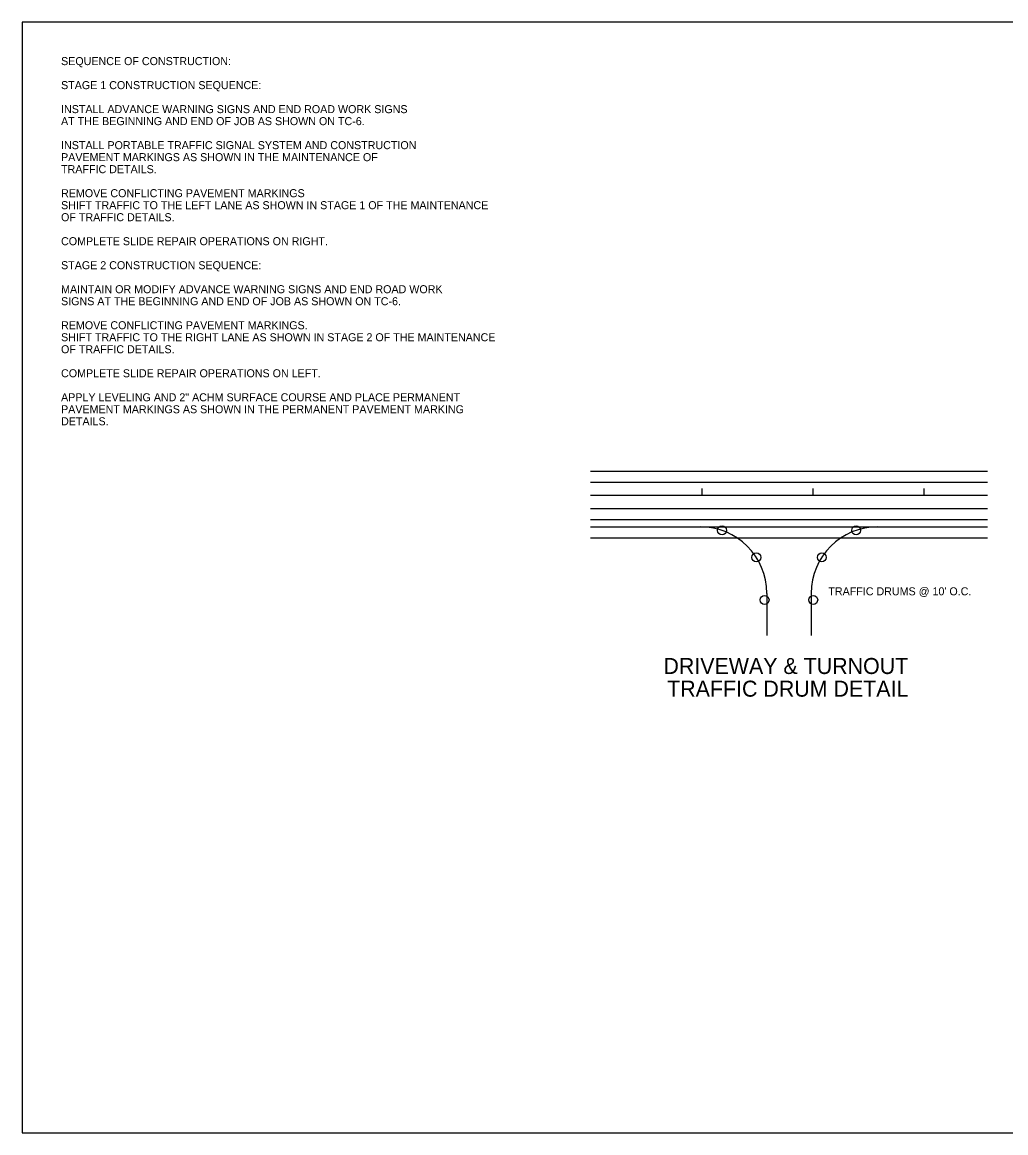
# Model space of a CAD drawing. Extents: x 1806907 to 1812607, y 675071 to 676228.
# Drawn here: x 1806907 to 1807792, y 675071 to 676070 of the extents above; entities that cross this region are included whole.
import ezdxf

# ---------------------------------------------------------------- set-up
doc = ezdxf.new("R2010")
doc.units = 0
for name, color, linetype in [('_STAGE 1 DRUMS', 7, 'Continuous'), ('Default', 7, 'Continuous'), ('DSN_DRFT_Named-Boundary', 7, 'Continuous'), ('DSN_DRWY_Driveway', 7, 'Continuous'), ('DSN_RDWY_Alignment', 7, 'Continuous'), ('DSN_RDWY_Alignment Annotation', 7, 'Continuous'), ('EX_DRIVEWAY', 7, 'Continuous'), ('S_PHOTO_CTL_ANNOT', 7, 'Continuous')]:
    doc.layers.add(name, color=color, linetype=linetype)

msp = doc.modelspace()

# ---------------------------------------------------------------- linework, layer by layer
at = {"layer": '_STAGE 1 DRUMS'}
for centre in [(1807536.68, 675613.14), (1807657.42, 675613.14), (1807567.54, 675588.86), (1807626.56, 675588.86), (1807575, 675550.51), (1807618.8, 675550.55)]:
    msp.add_circle(centre, 4, dxfattribs=at)
at = {"layer": 'DSN_DRFT_Named-Boundary'}
msp.add_lwpolyline([(1806906.68, 675071.2), (1808556.68, 675071.2), (1808556.68, 676070.26), (1806906.68, 676070.26)], close=True, dxfattribs=at)
at = {"layer": 'DSN_DRWY_Driveway'}
for p, q in [((1807418.43, 675616.44), (1807775.67, 675616.44)), ((1807418.43, 675606.44), (1807775.67, 675606.44))]:
    msp.add_line(p, q, dxfattribs=at)
at = {"layer": 'DSN_RDWY_Alignment'}
msp.add_line((1807418.43, 675644.68), (1807775.67, 675644.68), dxfattribs=at)
at = {"layer": 'DSN_RDWY_Alignment Annotation'}
for p, q in [((1807518.43, 675650.68), (1807518.43, 675644.68)), ((1807618.43, 675650.68), (1807618.43, 675644.68)), ((1807718.43, 675650.68), (1807718.43, 675644.68))]:
    msp.add_line(p, q, dxfattribs=at)
at = {"layer": 'EX_DRIVEWAY'}
for p, q in [((1807418.43, 675666.44), (1807775.67, 675666.44)), ((1807418.43, 675656.44), (1807775.67, 675656.44)), ((1807418.43, 675632.92), (1807775.67, 675632.92)), ((1807418.43, 675622.92), (1807775.67, 675622.92))]:
    msp.add_line(p, q, dxfattribs=at)
at = {"layer": 'S_PHOTO_CTL_ANNOT'}
for p, q in [((1807577.05, 675556.44), (1807577.05, 675518.44)), ((1807617.05, 675556.44), (1807617.05, 675518.44))]:
    msp.add_line(p, q, dxfattribs=at)
for centre, start, end in [((1807517.05, 675556.44), 0, 90), ((1807677.05, 675556.44), 90, 180)]:
    msp.add_arc(centre, 60, start, end, dxfattribs=at)

# ---------------------------------------------------------------- texts
at = {"layer": 'Default'}
for s, height, p in [('SEQUENCE OF CONSTRUCTION:', 7.2, (1806941.68, 676031.66)), ('STAGE 1 CONSTRUCTION SEQUENCE:', 7.2, (1806941.68, 676010.06)), ('INSTALL ADVANCE WARNING SIGNS AND END ROAD WORK SIGNS', 7.2, (1806941.68, 675988.46)), ('AT THE BEGINNING AND END OF JOB AS SHOWN ON TC-6.', 7.2, (1806941.68, 675977.66)), ('INSTALL PORTABLE TRAFFIC SIGNAL SYSTEM AND CONSTRUCTION', 7.2, (1806941.68, 675956.06)), ('PAVEMENT MARKINGS AS SHOWN IN THE MAINTENANCE OF', 7.2, (1806941.68, 675945.26)), ('TRAFFIC DETAILS.', 7.2, (1806941.68, 675934.46)), ('REMOVE CONFLICTING PAVEMENT MARKINGS', 7.2, (1806941.68, 675912.86)), ('SHIFT TRAFFIC TO THE LEFT LANE AS SHOWN IN STAGE 1 OF THE MAINTENANCE', 7.2, (1806941.68, 675902.06)), ('OF TRAFFIC DETAILS.', 7.2, (1806941.68, 675891.26)), ('COMPLETE SLIDE REPAIR OPERATIONS ON RIGHT.', 7.2, (1806941.68, 675869.66)), ('STAGE 2 CONSTRUCTION SEQUENCE:', 7.2, (1806941.68, 675848.06)), ('MAINTAIN OR MODIFY ADVANCE WARNING SIGNS AND END ROAD WORK ', 7.2, (1806941.68, 675826.46)), ('SIGNS AT THE BEGINNING AND END OF JOB AS SHOWN ON TC-6.', 7.2, (1806941.68, 675815.66)), ('REMOVE CONFLICTING PAVEMENT MARKINGS.', 7.2, (1806941.68, 675794.06)), ('SHIFT TRAFFIC TO THE RIGHT LANE AS SHOWN IN STAGE 2 OF THE MAINTENANCE', 7.2, (1806941.68, 675783.26)), ('OF TRAFFIC DETAILS.', 7.2, (1806941.68, 675772.46)), ('COMPLETE SLIDE REPAIR OPERATIONS ON LEFT.', 7.2, (1806941.68, 675750.86)), ('APPLY LEVELING AND 2" ACHM SURFACE COURSE AND PLACE PERMANENT ', 7.2, (1806941.68, 675729.26)), ('PAVEMENT MARKINGS AS SHOWN IN THE PERMANENT PAVEMENT MARKING', 7.2, (1806941.68, 675718.46)), ('DETAILS.', 7.2, (1806941.68, 675707.66)), ("TRAFFIC DRUMS @ 10' O.C.", 7.2, (1807632.42, 675554.71)), ('DRIVEWAY & TURNOUT ', 14.4, (1807483.94, 675483.93)), ('TRAFFIC DRUM DETAIL', 14.4, (1807487.29, 675463.53))]:
    msp.add_text(s, height=height, dxfattribs=at).set_placement(p)

doc.saveas('drawing.dxf')
